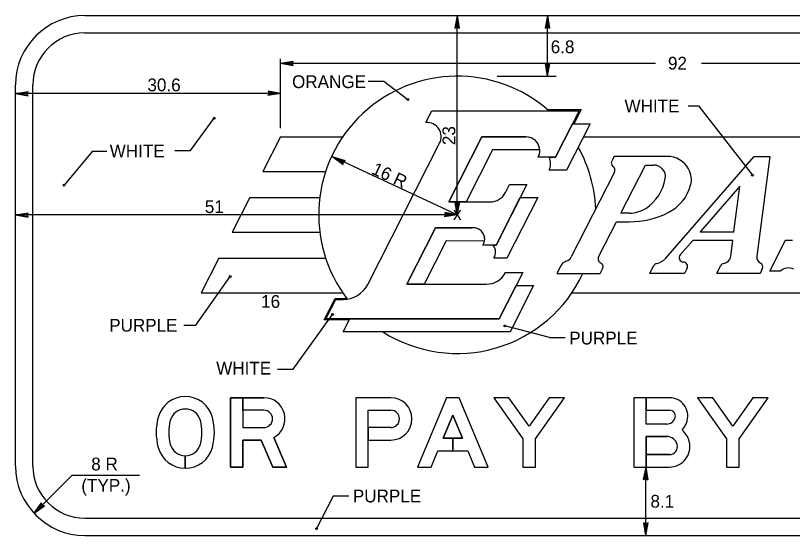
# Model space of a CAD drawing. Extents: x 60712 to 61344, y 9358 to 10016.
# Drawn here: x 60742.5 to 60912.9, y 9646 to 9760 of the extents above; entities that cross this region are included whole.
import ezdxf

# ---------------------------------------------------------------- set-up
doc = ezdxf.new("R2010")
doc.units = 0
for name, color, linetype in [('1', 7, 'Continuous'), ('52', 7, 'Continuous'), ('GSBWFill', 7, 'Continuous'), ('SignPanel', 7, 'Continuous')]:
    doc.layers.add(name, color=color, linetype=linetype)

msp = doc.modelspace()

# ---------------------------------------------------------------- linework, layer by layer
at = {"layer": '1'}
for p, q in [((60839.4, 9716.26), (60839.4, 9759.96)), ((60859.19, 9746.66), (60859.19, 9759.96)), ((60800.64, 9735.26), (60800.64, 9750.46)), ((60800.64, 9749.51), (60882.87, 9749.51)), ((60892.98, 9749.51), (60975.44, 9749.51)), ((60848.14, 9746.66), (60861.09, 9746.66)), ((60819.87, 9745.6), (60823.31, 9745.6)), ((60823.31, 9745.6), (60828.55, 9741.55)), ((60800.64, 9742.86), (60742.5, 9742.86)), ((60890.04, 9740.13), (60892.3, 9740.13)), ((60892.3, 9740.13), (60904.15, 9724.93)), ((60780.87, 9730.33), (60786.07, 9737.44)), ((60759.32, 9730.18), (60753.13, 9722.76)), ((60762.53, 9730.18), (60759.32, 9730.18)), ((60777.44, 9730.33), (60780.87, 9730.33)), ((60839.4, 9716.26), (60812.12, 9728.98)), ((60805.98, 9716.26), (60742.5, 9716.26)), ((60839.4, 9716.26), (60805.98, 9716.26)), ((60782.04, 9692.08), (60789.59, 9702.73)), ((60803.43, 9682.44), (60812.05, 9694.42)), ((60779.4, 9692.08), (60782.04, 9692.08)), ((60859.6, 9689.35), (60849.84, 9691.9)), ((60859.6, 9689.35), (60863.03, 9689.35)), ((60799.99, 9682.44), (60803.43, 9682.44)), ((60880.73, 9645.95), (60880.73, 9660.95)), ((60746.56, 9650.81), (60754.94, 9659.18)), ((60754.94, 9659.18), (60769.71, 9659.16)), ((60812.15, 9654.54), (60808.5, 9647.45)), ((60815.62, 9654.54), (60812.15, 9654.54))]:
    msp.add_line(p, q, dxfattribs=at)
for centre in [(60828.55, 9741.55), (60786.07, 9737.44), (60904.15, 9724.93), (60753.13, 9722.76), (60789.59, 9702.73), (60812.05, 9694.42), (60849.84, 9691.9), (60849.84, 9691.9), (60808.5, 9647.45)]:
    msp.add_circle(centre, 0.19, dxfattribs=at)
at = {"layer": '52'}
for p, q in [((60839.4, 9759.96), (60838.86, 9757.2)), ((60839.4, 9759.96), (60839.12, 9757.3)), ((60839.4, 9759.96), (60839.84, 9757.18)), ((60839.4, 9759.96), (60839.59, 9757.3)), ((60859.19, 9759.96), (60858.65, 9757.2)), ((60859.19, 9759.96), (60858.91, 9757.3)), ((60859.19, 9759.96), (60859.63, 9757.18)), ((60859.19, 9759.96), (60859.38, 9757.3)), ((60838.86, 9757.2), (60839.36, 9757.4)), ((60839.36, 9757.4), (60839.84, 9757.18)), ((60858.65, 9757.2), (60859.15, 9757.4)), ((60859.15, 9757.4), (60859.63, 9757.18)), ((60800.64, 9749.51), (60803.42, 9749.95)), ((60803.2, 9749.46), (60803.42, 9749.95)), ((60800.64, 9749.51), (60803.3, 9749.69)), ((60800.64, 9749.51), (60803.4, 9748.97)), ((60800.64, 9749.51), (60803.29, 9749.23)), ((60803.4, 9748.97), (60803.2, 9749.46)), ((60859.19, 9746.66), (60858.75, 9749.44)), ((60859.23, 9749.21), (60858.75, 9749.44)), ((60859.19, 9746.66), (60859, 9749.32)), ((60859.19, 9746.66), (60859.73, 9749.42)), ((60859.19, 9746.66), (60859.47, 9749.31)), ((60859.73, 9749.42), (60859.23, 9749.21)), ((60742.5, 9742.86), (60745.28, 9743.3)), ((60742.5, 9742.86), (60745.16, 9743.04)), ((60745.06, 9742.81), (60745.28, 9743.3)), ((60798.08, 9742.9), (60797.86, 9742.42)), ((60800.64, 9742.86), (60797.88, 9743.39)), ((60797.88, 9743.39), (60798.08, 9742.9)), ((60800.64, 9742.86), (60797.99, 9743.14)), ((60742.5, 9742.86), (60745.26, 9742.32)), ((60742.5, 9742.86), (60745.15, 9742.58)), ((60745.26, 9742.32), (60745.06, 9742.81)), ((60800.64, 9742.86), (60797.86, 9742.42)), ((60800.64, 9742.86), (60797.98, 9742.67)), ((60812.12, 9728.98), (60814.82, 9728.2)), ((60812.12, 9728.98), (60814.39, 9727.33)), ((60812.12, 9728.98), (60814.41, 9727.61)), ((60812.12, 9728.98), (60814.61, 9728.02)), ((60814.39, 9727.33), (60814.42, 9727.86)), ((60814.42, 9727.86), (60814.82, 9728.2)), ((60839.4, 9716.26), (60838.96, 9719.03)), ((60839.44, 9718.81), (60838.96, 9719.03)), ((60839.4, 9716.26), (60839.21, 9718.92)), ((60839.4, 9716.26), (60839.94, 9719.02)), ((60839.4, 9716.26), (60839.68, 9718.91)), ((60839.94, 9719.02), (60839.44, 9718.81)), ((60742.5, 9716.26), (60745.28, 9716.7)), ((60742.5, 9716.26), (60745.16, 9716.44)), ((60742.5, 9716.26), (60745.26, 9715.72)), ((60742.5, 9716.26), (60745.15, 9715.98)), ((60745.06, 9716.21), (60745.28, 9716.7)), ((60745.26, 9715.72), (60745.06, 9716.21)), ((60836.84, 9716.3), (60836.62, 9715.82)), ((60839.4, 9716.26), (60836.62, 9715.82)), ((60839.4, 9716.26), (60836.64, 9716.79)), ((60836.64, 9716.79), (60836.84, 9716.3)), ((60839.4, 9716.26), (60836.74, 9716.07)), ((60839.4, 9716.26), (60836.75, 9716.53)), ((60880.73, 9660.95), (60880.2, 9658.19)), ((60880.73, 9660.95), (60880.45, 9658.3)), ((60880.73, 9660.95), (60881.17, 9658.17)), ((60880.73, 9660.95), (60880.92, 9658.29)), ((60880.2, 9658.19), (60880.69, 9658.4)), ((60880.69, 9658.4), (60881.17, 9658.17)), ((60746.56, 9650.81), (60748.18, 9653.11)), ((60746.56, 9650.81), (60748.28, 9652.85)), ((60748.37, 9652.62), (60748.18, 9653.11)), ((60748.87, 9652.42), (60748.37, 9652.62)), ((60746.56, 9650.81), (60748.61, 9652.52)), ((60746.56, 9650.81), (60748.87, 9652.42)), ((60880.73, 9645.95), (60880.29, 9648.73)), ((60880.77, 9648.51), (60880.29, 9648.73)), ((60880.73, 9645.95), (60880.54, 9648.61)), ((60880.73, 9645.95), (60881.27, 9648.71)), ((60880.73, 9645.95), (60881.01, 9648.61)), ((60881.27, 9648.71), (60880.77, 9648.51))]:
    msp.add_line(p, q, dxfattribs=at)
at = {"layer": 'GSBWFill'}
for p, q in [((60819.88, 9673.42), (60824.82, 9673.42)), ((60819.88, 9673.42), (60824.82, 9673.42)), ((60819.88, 9673.42), (60824.82, 9673.42)), ((60819.88, 9666.88), (60824.82, 9666.88)), ((60779.74, 9660.69), (60779.74, 9663.42)), ((60779.74, 9663.42), (60779.74, 9660.69)), ((60779.74, 9660.69), (60779.74, 9663.42)), ((60779.74, 9663.42), (60779.74, 9660.69)), ((60878.11, 9660.95), (60885.94, 9660.95))]:
    msp.add_line(p, q, dxfattribs=at)
for points in [[(60796.97, 9676.16), (60789.62, 9676.16), (60789.62, 9660.95), (60792.36, 9660.95), (60792.36, 9666.88), (60796.39, 9666.88), (60798.95, 9660.95), (60801.94, 9660.95), (60799.14, 9667.42)], [(60799.14, 9667.42), (60801.94, 9660.95), (60798.95, 9660.95), (60796.39, 9666.88), (60792.36, 9666.88), (60792.36, 9660.95), (60789.62, 9660.95), (60789.62, 9676.16), (60792.36, 9676.16), (60792.36, 9669.62), (60796.97, 9669.62)], [(60799.14, 9667.42), (60801.94, 9660.95), (60798.95, 9660.95), (60796.39, 9666.88), (60792.36, 9666.88), (60792.36, 9660.95), (60789.62, 9660.95), (60789.62, 9676.16), (60792.36, 9676.16), (60792.36, 9669.62), (60796.97, 9669.62)], [(60792.36, 9673.42), (60792.36, 9676.16), (60796.97, 9676.16)], [(60792.36, 9673.42), (60792.36, 9676.16), (60796.97, 9676.16)], [(60824.82, 9676.16), (60817.14, 9676.16), (60817.14, 9660.95), (60819.88, 9660.95), (60819.88, 9666.88)], [(60824.82, 9676.16), (60817.14, 9676.16), (60817.14, 9660.95), (60819.88, 9660.95), (60819.88, 9673.42)], [(60824.82, 9676.16), (60817.14, 9676.16), (60817.14, 9660.95), (60819.88, 9660.95), (60819.88, 9673.42)], [(60885.94, 9676.16), (60878.11, 9676.16), (60878.11, 9660.95)], [(60885.35, 9670.38), (60880.84, 9670.38), (60880.84, 9676.16), (60878.11, 9676.16), (60878.11, 9660.95), (60880.84, 9660.95)], [(60885.35, 9670.38), (60880.84, 9670.38), (60880.84, 9676.16), (60878.11, 9676.16), (60878.11, 9660.95), (60880.84, 9660.95)], [(60885.94, 9676.16), (60880.84, 9676.16), (60880.84, 9673.42), (60885.94, 9673.42)], [(60885.94, 9676.16), (60880.84, 9676.16), (60880.84, 9673.42), (60885.94, 9673.42)], [(60796.97, 9673.42), (60792.36, 9673.42), (60792.36, 9669.62), (60796.97, 9669.62)], [(60796.97, 9673.42), (60792.36, 9673.42)], [(60796.97, 9673.42), (60792.36, 9673.42)], [(60824.82, 9669.62), (60819.88, 9669.62), (60819.88, 9673.42)], [(60885.35, 9670.38), (60880.84, 9670.38), (60880.84, 9673.42), (60885.94, 9673.42)], [(60824.82, 9669.62), (60819.88, 9669.62), (60819.88, 9666.88), (60824.82, 9666.88)], [(60824.82, 9669.62), (60819.88, 9669.62), (60819.88, 9666.88), (60824.82, 9666.88)], [(60885.35, 9667.64), (60880.84, 9667.64), (60880.84, 9663.69), (60885.94, 9663.69)], [(60880.84, 9660.95), (60880.84, 9667.64), (60885.35, 9667.64)], [(60880.84, 9660.95), (60880.84, 9667.64), (60885.35, 9667.64)], [(60885.94, 9663.69), (60880.84, 9663.69), (60880.84, 9660.95), (60885.94, 9660.95)], [(60885.94, 9663.69), (60880.84, 9663.69), (60880.84, 9660.95), (60885.94, 9660.95)]]:
    msp.add_lwpolyline(points, dxfattribs=at)
for points in [[(60835.14, 9664.53), (60841.71, 9664.53), (60843.21, 9660.95), (60846.18, 9660.95), (60839.79, 9676.16), (60837.06, 9676.16), (60830.67, 9660.95), (60833.64, 9660.95)], [(60840.56, 9667.26), (60838.43, 9667.26), (60838.43, 9664.53), (60841.71, 9664.53), (60843.21, 9660.95), (60846.18, 9660.95), (60839.79, 9676.16), (60837.06, 9676.16), (60830.67, 9660.95), (60833.64, 9660.95), (60835.14, 9664.53), (60838.42, 9664.53), (60838.42, 9667.26), (60836.29, 9667.26), (60838.42, 9672.35)], [(60840.56, 9667.26), (60838.43, 9667.26), (60838.43, 9664.53), (60841.71, 9664.53), (60843.21, 9660.95), (60846.18, 9660.95), (60839.79, 9676.16), (60837.06, 9676.16), (60830.67, 9660.95), (60833.64, 9660.95), (60835.14, 9664.53), (60838.42, 9664.53), (60838.42, 9667.26), (60836.29, 9667.26), (60838.42, 9672.35)], [(60856.52, 9667.11), (60862.9, 9676.16), (60859.55, 9676.16), (60855.15, 9669.92), (60850.74, 9676.16), (60847.39, 9676.16), (60853.78, 9667.11), (60853.78, 9660.95), (60856.52, 9660.95)], [(60856.52, 9667.11), (60862.9, 9676.16), (60859.55, 9676.16), (60855.15, 9669.92), (60850.74, 9676.16), (60847.39, 9676.16), (60853.78, 9667.11), (60853.78, 9660.95), (60856.52, 9660.95)], [(60856.52, 9667.11), (60862.9, 9676.16), (60859.55, 9676.16), (60855.15, 9669.92), (60850.74, 9676.16), (60847.39, 9676.16), (60853.78, 9667.11), (60853.78, 9660.95), (60856.52, 9660.95)], [(60901.22, 9667.11), (60907.6, 9676.16), (60904.25, 9676.16), (60899.85, 9669.92), (60895.44, 9676.16), (60892.09, 9676.16), (60898.48, 9667.11), (60898.48, 9660.95), (60901.22, 9660.95)], [(60901.22, 9667.11), (60907.6, 9676.16), (60904.25, 9676.16), (60899.85, 9669.92), (60895.44, 9676.16), (60892.09, 9676.16), (60898.48, 9667.11), (60898.48, 9660.95), (60901.22, 9660.95)], [(60901.22, 9667.11), (60907.6, 9676.16), (60904.25, 9676.16), (60899.85, 9669.92), (60895.44, 9676.16), (60892.09, 9676.16), (60898.48, 9667.11), (60898.48, 9660.95), (60901.22, 9660.95)], [(60840.56, 9667.26), (60838.42, 9672.35), (60836.29, 9667.26)]]:
    msp.add_lwpolyline(points, close=True, dxfattribs=at)
for centre, radius, start, end in [((60779.74, 9670.26), 6.16, 14.9618, 165.0382), ((60779.74, 9670.26), 6.16, 14.9618, 165.0382), ((60779.74, 9670.26), 6.16, 14.9618, 165.0382), ((60796.97, 9671.52), 4.64, 297.837, 90), ((60796.97, 9671.52), 4.64, 297.837, 90), ((60796.97, 9671.52), 4.64, 297.837, 90), ((60885.94, 9672.13), 4.03, 345.5225, 90), ((60885.94, 9672.13), 4.03, 345.5225, 90), ((60885.94, 9672.13), 4.03, 345.5225, 90), ((60779.74, 9670.26), 3.42, 14.9618, 165.0382), ((60779.74, 9670.26), 3.42, 14.9618, 165.0382), ((60779.74, 9670.26), 3.42, 14.9618, 165.0382), ((60796.97, 9671.52), 1.9, 270, 90), ((60796.97, 9671.52), 1.9, 270, 90), ((60796.97, 9671.52), 1.9, 270, 90), ((60885.94, 9672.13), 1.29, 345.5225, 90), ((60885.94, 9672.13), 1.29, 345.5225, 90), ((60885.94, 9672.13), 1.29, 345.5225, 90), ((60786.12, 9668.55), 12.77, 165.0382, 194.9618), ((60786.12, 9668.55), 12.77, 165.0382, 194.9618), ((60786.12, 9668.55), 12.77, 165.0382, 194.9618), ((60773.35, 9668.55), 12.77, 345.0382, 14.9618), ((60773.35, 9668.55), 12.77, 345.0382, 14.9618), ((60773.35, 9668.55), 12.77, 345.0382, 14.9618), ((60885.35, 9672.28), 1.9, 270, 345.5225), ((60885.35, 9672.28), 1.9, 270, 345.5225), ((60885.35, 9672.28), 1.9, 270, 345.5225), ((60786.12, 9668.55), 10.03, 165.0382, 194.9618), ((60786.12, 9668.55), 10.03, 165.0382, 194.9618), ((60786.12, 9668.55), 10.03, 165.0382, 194.9618), ((60773.35, 9668.55), 10.03, 345.0382, 14.9618), ((60773.35, 9668.55), 10.03, 345.0382, 14.9618), ((60773.35, 9668.55), 10.03, 345.0382, 14.9618), ((60885.35, 9672.28), 4.64, 316.7114, 345.5225), ((60885.35, 9672.28), 4.64, 316.7114, 345.5225), ((60885.35, 9672.28), 4.64, 316.7114, 345.5225), ((60885.35, 9665.29), 5.09, 14.4775, 48.4921), ((60885.35, 9665.29), 5.09, 14.4775, 48.4921), ((60885.35, 9665.29), 5.09, 14.4775, 48.4921), ((60885.35, 9665.29), 2.36, 14.4775, 90), ((60885.35, 9665.29), 2.36, 14.4775, 90), ((60885.35, 9665.29), 2.36, 14.4775, 90), ((60885.94, 9665.44), 4.49, 270, 14.4775), ((60885.94, 9665.44), 4.49, 270, 14.4775), ((60885.94, 9665.44), 4.49, 270, 14.4775), ((60779.74, 9666.85), 6.16, 194.9618, 345.0382), ((60779.74, 9666.85), 6.16, 194.9618, 270), ((60779.74, 9666.85), 6.16, 194.9618, 270), ((60779.74, 9666.85), 3.42, 194.9618, 345.0382), ((60779.74, 9666.85), 3.42, 194.9618, 270), ((60779.74, 9666.85), 3.42, 194.9618, 270), ((60779.74, 9666.85), 3.42, 270.0127, 345.0382), ((60779.74, 9666.85), 3.42, 270.0127, 345.0382), ((60779.74, 9666.85), 6.16, 270.0071, 345.0382), ((60779.74, 9666.85), 6.16, 270.0071, 345.0382), ((60885.94, 9665.44), 1.75, 270, 14.4775), ((60885.94, 9665.44), 1.75, 270, 14.4775), ((60885.94, 9665.44), 1.75, 270, 14.4775)]:
    msp.add_arc(centre, radius, start, end, dxfattribs=at)
for major_axis in [(0, 4.64), (0, 4.64), (0, 4.64), (0, 1.9), (0, 1.9), (0, 1.9)]:
    msp.add_ellipse((60824.82, 9671.52), major_axis=major_axis, ratio=0.999994, start_param=3.141593, end_param=6.283185, dxfattribs=at)
at = {"layer": 'SignPanel'}
for p, q in [((60757.7, 9759.96), (61000.9, 9759.96)), ((60757.7, 9756.16), (61000.9, 9756.16)), ((60742.5, 9661.16), (60742.5, 9744.76)), ((60746.3, 9661.16), (60746.3, 9744.76)), ((60832.53, 9736.51), (60833.82, 9739.06)), ((60833.82, 9739.06), (60866.12, 9739.06)), ((60859.18, 9739.34), (60866.59, 9739.34)), ((60866.12, 9739.06), (60860.95, 9728.9)), ((60866.59, 9739.34), (60864.99, 9736.21)), ((60860.94, 9728.89), (60864.67, 9736.21)), ((60860.94, 9728.89), (60864.67, 9736.21)), ((60868.51, 9736.21), (60863.33, 9726.05)), ((60868.51, 9736.21), (60863.33, 9726.05)), ((60864.67, 9736.21), (60868.51, 9736.21)), ((60864.67, 9736.21), (60868.51, 9736.21)), ((60800.64, 9733.36), (60796.77, 9725.76)), ((60800.64, 9733.36), (60814.27, 9733.36)), ((60844.77, 9733.36), (60837.51, 9719.11)), ((60837.51, 9719.11), (60844.77, 9733.36)), ((60837.51, 9719.11), (60844.77, 9733.36)), ((60854.45, 9733.36), (60844.77, 9733.36)), ((60844.77, 9733.36), (60854.45, 9733.36)), ((60844.77, 9733.36), (60854.45, 9733.36)), ((60867.05, 9733.36), (60975.44, 9733.36)), ((60819.76, 9701.01), (60835.53, 9731.96)), ((60847.15, 9730.51), (60841.35, 9719.11)), ((60847.15, 9730.51), (60841.35, 9719.11)), ((60857.49, 9730.51), (60847.15, 9730.51)), ((60857.49, 9730.51), (60847.15, 9730.51)), ((60860.95, 9728.9), (60857.15, 9728.9)), ((60859.53, 9728.89), (60860.94, 9728.89)), ((60859.53, 9728.89), (60860.94, 9728.89)), ((60873.79, 9729.08), (60873.27, 9728.07)), ((60885.43, 9729.08), (60873.79, 9729.08)), ((60885.13, 9706.77), (60904.54, 9729.08)), ((60904.54, 9729.08), (60907.96, 9729.08)), ((60907.96, 9729.08), (60905.11, 9707.22)), ((60863.33, 9726.05), (60859.53, 9726.05)), ((60863.33, 9726.05), (60859.53, 9726.05)), ((60875.28, 9716.64), (60880.66, 9727.18)), ((60880.66, 9727.18), (60882.49, 9727.18)), ((60796.77, 9725.76), (60810.52, 9725.76)), ((60873.82, 9725.49), (60864.41, 9707.03)), ((60854.66, 9722.91), (60847.89, 9709.61)), ((60849.98, 9721.18), (60850.86, 9722.91)), ((60850.86, 9722.91), (60854.66, 9722.91)), ((60901.35, 9722.53), (60892.68, 9712.55)), ((60900.06, 9712.55), (60901.35, 9722.53)), ((60793.87, 9720.06), (60790, 9712.46)), ((60793.87, 9720.06), (60809.24, 9720.06)), ((60837.51, 9719.11), (60846.6, 9719.11)), ((60841.35, 9719.11), (60837.51, 9719.11)), ((60841.35, 9719.11), (60837.51, 9719.11)), ((60847.89, 9709.61), (60853.21, 9720.06)), ((60847.89, 9709.61), (60853.21, 9720.06)), ((60857.05, 9720.06), (60850.27, 9706.76)), ((60857.05, 9720.06), (60850.27, 9706.76)), ((60853.21, 9720.06), (60857.05, 9720.06)), ((60853.21, 9720.06), (60857.05, 9720.06)), ((60877.16, 9716.64), (60875.28, 9716.64)), ((60870.38, 9707.03), (60874.31, 9714.74)), ((60874.31, 9714.74), (60877.16, 9714.74)), ((60790, 9712.46), (60809.24, 9712.46)), ((60834.61, 9713.41), (60828.31, 9701.06)), ((60828.31, 9701.06), (60834.61, 9713.41)), ((60828.31, 9701.06), (60834.61, 9713.41)), ((60842.94, 9713.41), (60834.61, 9713.41)), ((60834.61, 9713.41), (60842.59, 9713.38)), ((60834.61, 9713.41), (60842.59, 9713.38)), ((60892.68, 9712.55), (60900.06, 9712.55)), ((60836.99, 9710.55), (60832.15, 9701.06)), ((60836.99, 9710.55), (60832.15, 9701.06)), ((60845.38, 9710.52), (60836.99, 9710.55)), ((60845.38, 9710.52), (60836.99, 9710.55)), ((60891.03, 9710.65), (60888.28, 9707.49)), ((60899.86, 9710.65), (60891.03, 9710.65)), ((60899.41, 9707.22), (60899.86, 9710.65)), ((60907.94, 9703.91), (60911.39, 9710.68)), ((60911.39, 9710.68), (60912.92, 9710.68)), ((60847.89, 9709.61), (60845.03, 9709.61)), ((60847.29, 9709.61), (60847.89, 9709.61)), ((60847.29, 9709.61), (60847.89, 9709.61)), ((60787.1, 9706.76), (60783.23, 9699.16)), ((60787.1, 9706.76), (60810.52, 9706.76)), ((60850.27, 9706.76), (60847.42, 9706.76)), ((60850.27, 9706.76), (60847.42, 9706.76)), ((60862.11, 9705.11), (60861.25, 9703.43)), ((60870.75, 9703.43), (60871.27, 9704.45)), ((60881.64, 9703.43), (60882.47, 9705.06)), ((60889.8, 9704.53), (60889.24, 9703.43)), ((60896.3, 9703.43), (60897.14, 9705.08)), ((60906.3, 9704.41), (60905.8, 9703.43)), ((60910.25, 9703.91), (60907.94, 9703.91)), ((60853.77, 9703.61), (60848.59, 9693.46)), ((60849.96, 9703.61), (60853.77, 9703.61)), ((60861.25, 9703.43), (60870.75, 9703.43)), ((60889.24, 9703.43), (60881.64, 9703.43)), ((60905.8, 9703.43), (60896.3, 9703.43)), ((60828.31, 9701.06), (60845.75, 9701.06)), ((60832.15, 9701.06), (60828.31, 9701.06)), ((60832.15, 9701.06), (60828.31, 9701.06)), ((60848.59, 9693.46), (60852.31, 9700.77)), ((60848.59, 9693.46), (60852.31, 9700.77)), ((60856.15, 9700.77), (60850.97, 9690.61)), ((60856.15, 9700.77), (60850.97, 9690.61)), ((60852.31, 9700.77), (60856.15, 9700.77)), ((60852.31, 9700.77), (60856.15, 9700.77)), ((60783.23, 9699.16), (60814.27, 9699.16)), ((60864.53, 9699.16), (60958.02, 9699.16)), ((60810.18, 9693.21), (60812.59, 9697.94)), ((60810.59, 9693.46), (60812.75, 9697.69)), ((60812.59, 9697.94), (60814.34, 9697.94)), ((60812.75, 9697.69), (60814.34, 9697.69)), ((60815.71, 9693.21), (60810.18, 9693.21)), ((60848.59, 9693.46), (60810.59, 9693.46)), ((60814.39, 9690.61), (60815.84, 9693.46)), ((60814.39, 9690.61), (60815.84, 9693.46)), ((60815.84, 9693.46), (60848.59, 9693.46)), ((60815.84, 9693.46), (60848.59, 9693.46)), ((60850.97, 9690.61), (60814.39, 9690.61)), ((60850.97, 9690.61), (60814.39, 9690.61)), ((60757.7, 9649.76), (61000.9, 9649.76)), ((60757.7, 9645.96), (61000.9, 9645.96))]:
    msp.add_line(p, q, dxfattribs=at)
for centre, radius, start, end in [((60757.7, 9744.75), 15.2, 90, 180), ((60757.7, 9744.75), 11.4, 90, 180), ((60839.4, 9716.25), 30.4, 48.5904, 217.4727), ((60832.73, 9733.38), 3.14, 332.9998, 93.8045), ((60854.45, 9730.31), 3.04, 332.2089, 90), ((60854.45, 9730.31), 3.04, 3.5833, 90), ((60854.45, 9730.31), 3.04, 3.5833, 90), ((60839.4, 9716.25), 30.4, 2.4236, 29.2771), ((60856.84, 9727.46), 3.04, 332.2089, 27.9127), ((60856.84, 9727.46), 3.04, 332.2089, 27.9127), ((60874.12, 9727.63), 0.95, 152.9784, 231.1602), ((60885.43, 9723.66), 5.42, 29.4315, 90), ((60872.81, 9726.01), 1.14, 333.0027, 51.1602), ((60882.49, 9724.61), 2.57, 351.076, 90), ((60886, 9723.99), 4.75, 344.7074, 29.4315), ((60875.63, 9725.69), 9.5, 302.4206, 351.076), ((60881.42, 9725.24), 9.5, 296.6431, 344.7074), ((60846.6, 9722.9), 3.8, 270, 332.9883), ((60877.16, 9723.28), 6.65, 270, 302.4206), ((60877.16, 9733.73), 19, 270, 296.6431), ((60842.94, 9710.93), 2.47, 350.3502, 98.3344), ((60842.94, 9710.93), 2.47, 350.3502, 98.3344), ((60842.94, 9710.93), 2.47, 327.421, 90), ((60845.34, 9708.08), 2.47, 327.421, 37.9799), ((60845.34, 9708.08), 2.47, 327.421, 37.9799), ((60889, 9706.86), 0.95, 138.9824, 268.6869), ((60897.53, 9707.46), 1.9, 279.2397, 352.5632), ((60906.62, 9707.02), 1.52, 172.5884, 241.8673), ((60863.8, 9704.24), 1.9, 106.4317, 152.9742), ((60862.72, 9707.89), 1.9, 286.4317, 332.9959), ((60871.23, 9706.59), 0.95, 152.9884, 244.7832), ((60870.42, 9704.87), 0.95, 333.0239, 64.7832), ((60883.31, 9704.62), 0.95, 102.7162, 153.0239), ((60882.27, 9709.26), 3.8, 282.7162, 318.9966), ((60888.95, 9704.96), 0.95, 332.9784, 88.6869), ((60897.99, 9704.65), 0.95, 99.2397, 153.0239), ((60905.45, 9704.84), 0.95, 332.9784, 61.8673), ((60912.07, 9701.96), 2.66, 64.3795, 133.1892), ((60839.4, 9716.25), 30.4, 237.5383, 335.047), ((60845.75, 9705.8), 4.75, 270, 332.5096), ((60814.34, 9703.77), 6.08, 270, 332.9991), ((60814.34, 9703.77), 5.83, 270, 277.5038), ((60757.7, 9661.15), 15.2, 180, 270), ((60757.7, 9661.15), 11.4, 180, 270)]:
    msp.add_arc(centre, radius, start, end, dxfattribs=at)

# ---------------------------------------------------------------- texts
at = {"layer": '1'}
for s, p in [('6.8', (60859.89, 9751.7)), ('92', (60885.61, 9748.11)), ('ORANGE', (60803.15, 9744.05)), ('30.6', (60771.43, 9743.35)), ('WHITE', (60876.09, 9738.73)), ('WHITE', (60763.15, 9728.87)), ('51', (60784.02, 9716.65)), ('x', (60838.47, 9715.14)), ('16', (60796.37, 9695.87)), ('PURPLE', (60763.04, 9690.65)), ('PURPLE', (60863.96, 9687.83)), ('WHITE', (60786.52, 9681.24)), ('PURPLE', (60816.49, 9653.2)), ('8.1', (60881.77, 9652.05))]:
    msp.add_text(s, height=2.8, dxfattribs=at).set_placement(p)
for s, rotation, p in [('23', 90, (60838.95, 9731.55)), ('16 R', 334.9991, (60820.38, 9725.36)), ('8 R', 0.165, (60759.11, 9660.21)), ('(TYP.)', 0.165, (60756.93, 9655.51))]:
    msp.add_text(s, height=2.8, rotation=rotation, dxfattribs=at).set_placement(p)

doc.saveas('drawing.dxf')
